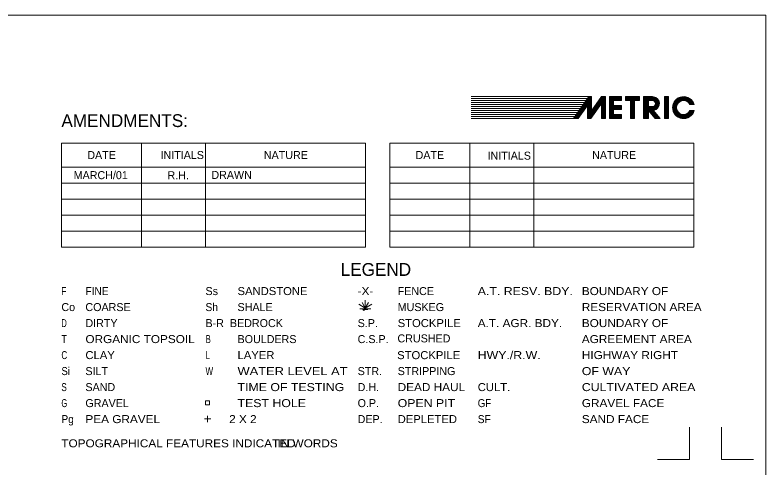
# Model space of a CAD drawing. Extents: x -496 to 480, y -450 to 700.
# Drawn here: x -19 to 450, y 416.9 to 700 of the extents above; entities that cross this region are included whole.
import ezdxf
from ezdxf.enums import TextEntityAlignment as Align

# ---------------------------------------------------------------- set-up
doc = ezdxf.new("R2010")
doc.units = 0
doc.header["$LTSCALE"] = 2
doc.header["$PDMODE"] = 32
doc.header["$PDSIZE"] = 1
doc.layers.add('1', color=7, linetype='Continuous', lineweight=13)

msp = doc.modelspace()

# ---------------------------------------------------------------- linework, layer by layer
at = {"layer": '1'}
for p, q in [((339.376, 648.989), (265.976, 648.989)), ((338.501, 647.739), (265.976, 647.739)), ((329.726, 635.239), (339.376, 648.989)), ((340.976, 640.064), (347.226, 648.989)), ((349.726, 648.989), (347.226, 648.989)), ((349.726, 635.239), (349.726, 648.989)), ((362.226, 648.989), (362.226, 646.489)), ((379.026, 648.989), (373.476, 648.989)), ((337.626, 646.489), (265.976, 646.489)), ((336.751, 645.239), (265.976, 645.239)), ((335.876, 643.989), (265.976, 643.989)), ((335.001, 642.739), (265.976, 642.739)), ((332.776, 635.239), (338.476, 643.364)), ((338.476, 635.239), (338.476, 643.389)), ((340.676, 635.264), (347.226, 644.614)), ((347.226, 635.239), (347.226, 644.614)), ((354.726, 646.489), (354.726, 643.364)), ((362.226, 646.489), (365.351, 646.489)), ((367.851, 646.489), (370.976, 646.489)), ((376.601, 646.489), (379.151, 646.489)), ((376.601, 642.739), (376.601, 646.489)), ((376.601, 642.739), (379.151, 642.739)), ((402.426, 643.989), (405.076, 643.989)), ((334.126, 641.489), (265.976, 641.489)), ((333.251, 640.239), (265.976, 640.239)), ((332.376, 638.989), (265.976, 638.989)), ((354.726, 640.864), (354.726, 637.739)), ((376.601, 640.239), (380.726, 635.239)), ((376.601, 635.239), (376.601, 640.239)), ((379.801, 640.289), (383.951, 635.239)), ((402.426, 640.239), (405.101, 640.239)), ((331.501, 637.739), (265.976, 637.739)), ((330.626, 636.489), (265.976, 636.489)), ((329.726, 635.239), (265.976, 635.239)), ((329.726, 635.239), (332.776, 635.239)), ((338.476, 635.239), (340.676, 635.239)), ((349.726, 635.239), (347.226, 635.239)), ((352.226, 635.239), (359.726, 635.239)), ((380.726, 635.239), (383.951, 635.239)), ((199.983, 619.973), (9.983, 619.973)), ((9.983, 619.973), (9.983, 554.973)), ((59.983, 619.973), (59.983, 554.973)), ((99.983, 619.973), (99.983, 554.973)), ((199.983, 554.973), (199.983, 619.973)), ((404.983, 619.973), (214.983, 619.973)), ((214.983, 619.973), (214.983, 554.973)), ((264.983, 619.973), (264.983, 554.973)), ((304.983, 619.973), (304.983, 554.973)), ((404.983, 554.973), (404.983, 619.973)), ((9.983, 604.973), (199.983, 604.973)), ((214.983, 604.973), (404.983, 604.973)), ((9.983, 594.973), (199.983, 594.973)), ((214.983, 594.973), (404.983, 594.973)), ((9.983, 584.973), (199.983, 584.973)), ((214.983, 584.973), (404.983, 584.973)), ((9.983, 574.973), (199.983, 574.973)), ((214.983, 574.973), (404.983, 574.973)), ((9.983, 564.973), (199.983, 564.973)), ((214.983, 564.973), (404.983, 564.973)), ((214.983, 554.973), (404.983, 554.973)), ((199.76, 516.875), (199.76, 521.875)), ((199.76, 516.875), (195.76, 519.375)), ((196.26, 516.375), (203.26, 516.375)), ((199.76, 516.875), (197.76, 520.375)), ((198.26, 515.875), (201.26, 515.875)), ((199.76, 516.875), (201.76, 520.375)), ((199.76, 516.875), (203.76, 519.375)), ((103.353, 447.618), (99.353, 447.618)), ((101.291, 449.597), (101.291, 445.597)), ((402.281, 422.339), (402.281, 442.339)), ((422.281, 422.339), (422.281, 442.339)), ((402.281, 422.339), (382.281, 422.339)), ((422.281, 422.339), (442.281, 422.339))]:
    msp.add_line(p, q, dxfattribs=at)
for points in [[(449.983, -450.027), (449.983, 399.973), (449.983, 699.973), (-450.017, 699.973), (-450.017, 49.973), (-450.017, -450.027)], [(329.901, 635.339), (339.401, 648.889), (340.901, 648.889), (340.901, 639.839), (347.251, 648.839), (349.626, 648.889), (349.676, 635.339), (347.351, 635.314), (347.301, 644.789), (340.576, 635.339), (338.576, 635.314), (338.576, 643.539), (332.701, 635.339), (330.076, 635.314), (339.501, 648.739), (340.801, 648.739), (340.776, 639.664), (347.276, 648.664), (349.526, 648.739), (349.651, 635.564), (347.501, 635.464), (347.426, 644.989), (340.526, 635.489), (338.726, 635.439), (338.676, 643.764), (332.651, 635.464), (330.301, 635.439), (339.576, 648.539), (340.651, 648.564), (340.651, 639.489), (347.351, 648.489), (349.301, 648.564), (349.476, 635.739), (347.726, 635.639), (347.626, 645.314), (340.451, 635.714), (338.926, 635.639), (338.876, 644.139), (332.501, 635.689), (330.701, 635.639)], [(330.701, 635.639), (339.651, 648.239), (340.326, 648.264), (340.476, 639.239), (347.526, 648.239), (349.126, 648.289), (349.226, 635.939), (348.001, 635.939), (347.851, 645.664), (340.326, 635.989), (339.151, 635.864), (339.126, 644.464), (332.401, 635.939), (331.076, 635.839), (339.651, 647.914), (340.151, 647.914), (340.251, 638.889), (347.601, 647.964), (348.926, 648.014), (349.026, 636.164), (348.251, 636.139), (348.051, 646.014), (340.226, 636.239), (339.351, 636.089), (339.326, 644.789), (332.226, 636.164), (331.476, 636.064), (339.701, 647.664), (339.926, 647.689), (340.126, 638.764), (347.751, 647.839), (348.701, 647.739), (348.826, 636.364), (348.476, 636.364), (348.176, 646.314), (340.126, 636.464), (339.551, 636.339), (339.426, 645.114), (332.201, 636.339), (331.851, 636.289)], [(331.851, 636.289), (339.701, 647.264), (339.926, 638.564), (347.826, 647.614), (348.451, 647.589), (348.701, 636.589), (348.251, 646.639), (340.126, 636.689), (339.726, 636.589), (339.576, 645.539), (332.301, 636.639), (339.526, 646.714), (339.576, 645.814), (335.101, 640.239), (339.401, 646.164), (339.401, 645.914), (338.176, 644.289)], [(340.976, 640.039), (340.976, 648.989), (339.376, 648.989)], [(339.901, 638.414), (339.926, 636.839), (348.276, 646.889), (348.326, 647.439), (347.951, 647.439), (340.126, 638.539), (340.151, 637.314), (348.176, 647.064), (348.051, 647.214), (340.326, 638.539), (340.401, 637.839), (347.851, 646.839), (340.501, 638.639), (340.526, 638.389), (344.426, 642.914)], [(352.226, 635.239), (352.226, 648.989), (359.726, 648.989)], [(352.376, 648.914), (359.651, 648.864), (359.676, 646.614), (354.626, 646.589), (354.626, 643.289), (359.651, 643.289), (359.651, 640.989), (354.651, 640.939), (354.626, 637.614), (359.676, 637.639), (359.651, 635.339), (352.351, 635.314), (352.376, 648.789), (359.551, 648.739), (359.551, 646.764), (354.501, 646.714), (354.501, 643.214), (359.551, 643.164), (359.551, 641.114), (354.551, 641.064), (354.526, 637.439), (359.551, 637.514), (359.501, 635.439), (352.501, 635.439), (352.576, 648.639), (359.401, 648.564), (359.426, 646.914), (354.376, 646.839), (354.351, 643.064), (359.426, 643.039), (359.376, 641.289), (354.401, 641.239), (354.376, 637.239), (359.401, 637.339), (359.376, 635.589), (352.701, 635.614), (352.726, 648.439), (359.226, 648.414), (359.251, 647.064), (354.251, 647.039)], [(354.251, 647.039), (354.176, 642.864), (359.251, 642.864), (359.176, 641.439), (354.251, 641.389), (354.201, 637.064), (359.201, 637.114), (359.176, 635.739), (352.926, 635.814), (352.976, 648.214), (359.026, 648.239), (359.076, 647.289), (354.076, 647.214), (354.001, 642.689), (359.051, 642.664), (359.026, 641.639), (354.076, 641.564), (354.026, 636.864), (359.051, 636.939), (359.026, 635.989), (353.126, 636.039), (353.226, 647.989), (358.801, 648.039), (358.826, 647.464), (353.926, 647.389), (353.851, 642.489), (358.876, 642.539), (358.801, 641.814), (353.951, 641.689), (353.851, 636.714), (358.901, 636.764), (358.901, 636.214), (353.351, 636.214), (353.476, 647.714), (358.601, 647.889), (358.626, 647.639), (353.776, 647.514), (353.751, 642.364), (358.626, 642.389), (358.601, 642.014)], [(358.601, 642.014), (353.826, 641.864), (353.726, 636.564), (358.701, 636.639), (358.701, 636.389), (353.551, 636.439), (353.626, 641.989), (358.376, 642.164), (358.326, 642.289), (353.576, 642.264), (353.676, 647.564)], [(359.726, 648.989), (359.726, 646.489), (354.726, 646.489)], [(370.976, 646.489), (370.976, 648.989), (362.226, 648.989)], [(362.351, 648.864), (370.851, 648.889), (370.851, 646.639), (367.701, 646.639), (367.751, 635.414), (365.451, 635.314), (365.451, 646.564), (362.351, 646.589), (362.351, 648.764), (370.801, 648.789), (370.726, 646.789), (367.601, 646.764), (367.676, 635.539), (365.576, 635.414), (365.626, 646.739), (362.476, 646.739), (362.476, 648.639), (370.626, 648.639), (370.576, 646.989), (367.426, 646.864), (367.526, 635.739), (365.751, 635.614), (365.776, 646.864), (362.701, 646.939), (362.726, 648.439), (370.451, 648.489), (370.376, 647.114), (367.276, 646.989), (367.376, 635.914), (365.901, 635.789), (365.951, 647.064), (362.901, 647.114), (362.901, 648.264), (370.201, 648.289), (370.201, 647.364), (367.076, 647.189), (367.226, 636.114), (366.126, 635.989), (366.101, 647.264), (363.101, 647.314)], [(363.101, 647.314), (363.151, 648.089), (369.976, 648.164), (369.926, 647.489), (366.876, 647.364), (367.026, 636.339), (366.351, 636.239), (366.276, 647.439), (363.326, 647.514), (363.401, 647.939), (369.751, 648.039), (369.701, 647.714), (366.726, 647.539), (366.851, 636.564), (366.476, 636.489), (366.426, 647.664), (363.701, 647.664), (363.751, 647.839), (369.451, 647.914), (369.426, 647.814), (366.601, 647.664), (366.626, 636.689)], [(373.476, 648.989), (373.476, 635.239), (376.601, 635.239)], [(373.601, 648.914), (378.976, 648.889), (380.101, 648.739), (381.101, 648.364), (381.826, 647.789), (382.451, 647.189), (382.901, 646.414), (383.301, 645.389), (383.301, 644.439), (383.126, 643.214), (382.651, 642.314), (381.926, 641.489), (381.051, 640.889), (380.401, 640.639), (379.651, 640.389), (380.026, 639.714), (380.576, 639.189), (383.701, 635.339), (380.801, 635.314), (376.501, 640.464), (376.526, 635.339), (373.551, 635.314), (373.551, 648.864), (379.026, 648.789), (380.076, 648.639), (380.926, 648.314), (382.276, 647.214), (383.151, 645.364), (383.026, 643.314), (382.601, 642.464), (381.901, 641.614), (381.051, 640.989), (379.576, 640.464), (383.501, 635.414), (380.951, 635.439), (376.351, 640.739), (376.401, 635.489), (373.701, 635.439), (373.701, 648.739), (379.151, 648.664), (380.076, 648.489), (380.851, 648.189), (382.126, 647.139), (383.026, 645.389), (382.951, 643.539), (382.501, 642.564), (381.901, 641.739), (381.051, 641.114), (379.401, 640.614), (383.201, 635.564), (381.001, 635.564), (376.226, 640.889), (376.276, 635.614), (373.826, 635.539), (373.826, 648.614), (379.126, 648.489), (380.676, 648.089), (382.026, 647.139), (382.876, 645.439), (382.801, 643.664), (382.401, 642.664), (381.801, 641.889), (380.951, 641.189), (379.226, 640.764), (382.901, 635.689), (381.101, 635.689), (376.051, 641.064), (376.126, 635.789), (373.976, 635.689), (373.976, 648.439), (379.101, 648.364), (380.551, 647.989), (381.851, 647.089), (382.776, 645.439), (382.701, 643.764), (382.326, 642.889), (381.726, 642.064), (380.901, 641.339), (379.026, 640.939), (382.601, 635.789), (381.126, 635.814), (375.876, 641.239), (375.976, 635.939), (374.126, 635.864), (374.126, 648.239), (379.026, 648.239), (380.251, 647.914), (381.676, 647.014), (382.576, 645.414), (382.601, 643.914), (382.276, 642.989), (381.651, 642.214), (380.826, 641.514), (378.851, 641.064), (382.351, 635.939), (381.176, 635.989), (375.776, 641.514), (375.826, 636.089), (374.251, 636.014), (374.276, 648.039), (378.976, 648.114)], [(378.976, 648.114), (379.026, 648.114), (380.201, 647.764), (381.526, 646.939), (382.401, 645.489), (382.401, 643.964), (382.076, 643.114), (380.826, 641.764), (378.601, 641.264), (382.001, 636.114), (381.351, 636.114), (375.676, 641.789), (375.676, 636.264), (374.376, 636.189), (374.451, 647.864), (378.926, 647.939), (380.176, 647.689), (381.351, 646.914), (382.151, 645.414), (382.201, 644.014), (381.901, 643.214), (380.726, 641.989), (378.401, 641.389), (381.676, 636.314), (381.501, 636.189), (375.526, 642.064), (375.476, 636.414), (374.551, 636.339), (374.651, 647.739), (379.976, 647.614), (381.151, 646.914), (382.001, 645.414), (382.051, 644.139), (381.726, 643.339), (380.651, 642.139), (378.226, 641.589), (381.401, 636.464), (375.401, 642.364), (375.376, 636.614), (374.676, 636.539), (374.901, 647.589), (379.826, 647.414), (380.851, 646.889), (381.801, 645.439), (381.901, 644.389), (381.576, 643.539), (380.576, 642.414), (378.051, 641.739), (380.676, 637.364), (375.376, 642.614), (375.226, 636.739), (374.851, 636.739), (375.076, 647.339), (379.601, 647.314), (380.676, 646.839), (381.626, 645.414), (381.726, 644.464), (381.376, 643.589), (380.501, 642.589), (377.826, 641.864), (380.026, 638.189), (375.251, 642.889), (375.076, 636.939), (374.926, 636.989), (375.226, 647.189), (379.526, 647.139), (380.551, 646.714), (381.401, 645.414), (381.551, 644.614), (380.376, 642.739), (377.726, 642.039), (379.276, 639.239), (375.351, 643.039), (375.426, 646.989), (379.476, 646.989), (380.526, 646.639), (381.251, 645.489), (381.326, 644.614), (380.276, 642.914), (377.551, 642.239), (378.601, 640.139), (375.576, 643.139), (375.676, 646.839), (379.451, 646.839), (380.476, 646.514), (381.101, 645.414), (381.051, 644.489), (380.876, 645.464), (380.501, 646.039), (380.151, 646.339), (379.476, 646.514), (378.751, 646.639), (377.601, 646.614), (376.476, 646.614), (376.501, 642.714), (378.626, 642.664), (377.376, 642.339), (378.126, 640.764), (375.726, 643.164), (375.876, 646.714), (379.451, 646.714)], [(386.776, 648.839), (388.951, 648.864), (389.001, 635.364), (386.701, 635.364), (386.676, 648.739), (388.851, 648.764), (388.876, 635.489), (386.826, 635.439), (386.801, 648.614), (388.776, 648.639), (388.776, 635.664), (386.976, 635.589), (386.926, 648.464), (388.626, 648.464), (388.601, 635.764), (387.126, 635.764), (387.101, 648.364), (388.501, 648.364), (388.451, 635.939), (387.301, 635.964), (387.301, 648.214), (388.401, 648.214), (388.301, 636.089), (387.426, 636.089), (387.476, 648.064), (388.251, 648.039), (388.151, 636.214), (387.576, 636.214), (387.676, 647.914), (388.126, 647.889), (388.001, 636.339), (387.776, 636.389), (387.826, 647.764), (387.976, 647.714), (387.901, 636.539)], [(404.901, 644.089), (404.451, 645.189), (403.851, 646.164), (403.151, 646.914), (402.301, 647.639), (401.151, 648.289), (400.126, 648.614), (398.801, 648.814), (397.351, 648.689), (395.876, 648.339), (394.601, 647.639), (393.601, 646.764), (392.776, 645.664), (392.176, 644.564), (391.801, 642.964), (391.801, 641.264), (392.176, 639.789), (392.726, 638.564), (393.351, 637.739), (394.101, 637.014), (394.976, 636.389), (395.901, 635.914), (397.126, 635.489), (398.726, 635.389), (400.151, 635.589), (401.301, 635.989), (402.326, 636.564), (403.326, 637.414), (404.001, 638.264), (404.426, 639.139), (404.801, 640.064), (402.526, 640.089), (401.776, 638.989), (400.776, 638.289), (399.801, 637.814), (398.476, 637.564), (397.026, 637.839), (396.126, 638.289), (395.276, 638.939), (394.551, 639.939), (394.076, 641.189), (394.051, 642.814), (394.276, 643.889), (394.901, 644.889), (395.601, 645.614), (396.476, 646.164), (397.376, 646.489), (398.426, 646.614), (399.526, 646.489), (400.426, 646.214), (401.176, 645.764), (401.801, 645.239), (402.301, 644.664), (402.576, 644.139), (404.726, 644.164), (404.251, 645.214), (403.651, 646.164), (402.276, 647.489), (401.126, 648.114), (399.351, 648.614), (397.876, 648.564), (396.551, 648.339), (395.226, 647.814), (394.351, 647.264), (393.451, 646.339), (392.676, 645.139), (392.176, 643.939), (391.976, 642.239), (392.076, 640.689), (392.576, 639.164), (393.476, 637.864), (394.526, 636.864), (395.701, 636.164), (397.201, 635.639), (398.626, 635.514), (400.251, 635.764), (401.276, 636.089), (402.301, 636.789), (403.176, 637.439), (403.726, 638.164), (404.376, 639.239), (404.551, 639.964), (402.626, 639.989), (402.076, 639.064), (400.751, 638.139), (399.826, 637.689), (398.526, 637.389), (396.976, 637.739), (395.601, 638.439), (394.651, 639.639), (394.076, 640.764), (393.876, 642.139), (394.151, 643.989), (394.726, 644.964), (395.826, 646.014), (397.051, 646.539), (398.351, 646.789), (399.826, 646.614), (401.026, 646.064), (401.701, 645.614), (402.226, 645.014)], [(402.226, 645.014), (402.301, 645.014), (402.676, 644.239), (404.476, 644.264), (404.026, 645.314), (402.876, 646.664), (401.901, 647.489), (400.851, 648.089), (399.251, 648.514), (396.976, 648.264), (395.201, 647.614), (394.051, 646.639), (393.151, 645.614), (392.526, 644.239), (392.176, 642.439), (392.326, 640.539), (392.676, 639.489), (392.951, 638.864), (393.701, 637.864), (394.851, 636.839), (397.101, 635.814), (398.651, 635.664), (401.026, 636.164), (403.076, 637.564), (403.901, 638.814), (404.326, 639.814), (403.476, 639.789), (402.726, 639.839), (402.201, 638.889), (400.776, 637.964), (399.526, 637.414), (398.251, 637.264), (396.651, 637.714), (395.476, 638.364), (394.451, 639.714), (393.901, 640.864), (393.701, 642.264), (393.976, 643.889), (394.651, 645.264), (395.701, 646.214), (397.376, 646.789), (398.851, 646.914), (400.251, 646.614), (401.626, 645.914), (402.426, 645.164), (402.801, 644.439), (404.226, 644.414), (403.426, 645.739), (402.676, 646.614), (401.826, 647.314), (400.851, 647.939), (399.276, 648.314), (397.051, 648.089), (395.226, 647.364), (393.976, 646.314), (393.201, 645.414), (392.651, 643.839), (392.426, 642.514), (392.451, 641.239), (392.651, 640.089), (393.101, 639.039), (393.651, 638.239), (394.376, 637.564), (395.226, 636.839), (396.351, 636.314), (397.451, 635.914), (398.701, 635.839), (400.826, 636.364), (402.976, 637.639), (403.801, 638.964), (404.026, 639.714), (402.851, 639.664), (402.326, 638.814), (401.226, 638.164), (399.651, 637.239), (398.226, 637.114), (397.101, 637.389), (395.976, 637.889), (394.801, 638.989), (394.101, 640.014), (393.601, 641.664), (393.676, 643.264), (394.101, 644.689), (395.376, 646.214), (396.876, 646.764), (398.751, 647.064), (400.326, 646.764), (401.751, 646.089), (402.651, 645.189), (402.951, 644.539), (403.876, 644.614), (403.051, 645.989), (402.201, 646.789), (400.851, 647.739), (399.376, 648.189), (397.151, 647.889), (395.451, 647.239), (394.076, 646.164), (393.251, 645.039), (392.701, 643.014), (392.651, 641.564)], [(392.651, 641.564), (392.676, 641.614), (392.951, 639.914), (393.451, 638.964), (394.051, 638.214), (394.926, 637.289), (395.951, 636.764), (396.601, 636.389), (397.801, 636.039), (398.776, 635.989), (400.726, 636.464), (402.951, 637.739), (403.651, 639.064), (403.726, 639.564), (403.026, 639.539), (402.576, 638.814), (399.876, 637.114), (398.026, 637.014), (396.051, 637.664), (394.476, 639.139), (393.526, 641.439), (393.651, 643.889), (394.476, 645.514), (395.726, 646.539), (397.351, 646.989), (398.701, 647.239), (400.476, 646.939), (401.751, 646.339), (402.526, 645.664), (402.851, 645.114), (403.076, 644.739), (403.551, 644.789), (402.926, 645.989), (401.801, 646.914), (400.676, 647.639), (399.376, 648.039), (397.176, 647.789), (395.676, 647.164), (394.226, 646.139), (393.501, 645.039), (392.901, 643.314), (392.826, 641.639), (393.126, 639.989), (393.851, 638.689), (394.951, 637.514), (396.001, 636.989), (396.726, 636.564), (398.626, 636.139), (400.701, 636.614), (402.776, 637.864), (403.476, 639.064), (403.601, 639.464), (403.251, 639.389), (402.751, 638.739), (400.001, 637.014), (398.001, 636.889), (395.901, 637.564), (394.326, 639.064), (393.376, 641.464), (393.576, 643.939), (394.301, 645.589), (395.526, 646.689), (398.576, 647.339), (400.751, 647.089), (401.751, 646.489), (402.601, 645.914), (403.076, 645.039), (403.326, 644.914), (402.851, 645.939), (400.926, 647.289), (399.526, 647.889), (397.401, 647.714), (395.626, 647.039), (394.251, 646.039), (393.576, 644.889), (393.026, 643.239), (392.951, 641.714), (393.276, 640.314), (393.801, 639.139), (394.376, 638.339), (395.076, 637.639), (396.901, 636.764), (398.651, 636.314), (400.576, 636.789), (402.601, 637.914), (403.351, 639.139), (402.501, 638.339), (401.601, 637.789), (400.101, 636.864), (398.051, 636.764), (395.801, 637.439), (394.176, 639.064), (393.226, 641.539), (393.501, 644.014), (394.126, 645.639), (395.451, 646.739), (397.026, 647.189), (398.576, 647.489), (399.776, 647.389), (400.526, 647.289), (399.551, 647.639)], [(399.551, 647.639), (398.601, 647.639), (397.451, 647.489), (395.901, 647.064)], [(354.726, 640.864), (359.726, 640.864), (359.726, 643.364), (354.726, 643.364)], [(367.851, 646.489), (367.851, 635.239), (365.351, 635.239), (365.351, 646.489)], [(376.026, 646.614), (375.901, 643.214), (377.551, 641.614), (377.251, 642.364), (377.776, 642.614), (376.826, 642.614), (377.201, 642.164)], [(376.151, 646.564), (376.051, 643.314), (376.376, 643.064), (376.351, 646.564), (376.251, 643.389)], [(379.451, 646.714), (379.401, 646.739), (380.451, 646.289)], [(402.751, 638.439), (402.076, 637.814), (400.676, 637.089), (399.226, 636.639), (398.501, 636.639), (396.951, 636.914), (395.751, 637.364), (394.201, 638.764), (393.101, 641.589), (393.401, 643.964), (393.901, 645.289)], [(354.726, 637.739), (359.726, 637.739), (359.726, 635.239)], [(9.983, 554.973), (99.983, 554.973), (199.983, 554.973)]]:
    msp.add_lwpolyline(points, dxfattribs=at)
for points in [[(386.601, 635.239), (386.601, 648.989), (389.101, 648.989), (389.101, 635.239)], [(99.967, 456.301), (99.967, 458.832), (102.499, 458.832), (102.499, 456.301)]]:
    msp.add_lwpolyline(points, close=True, dxfattribs=at)
for centre, radius, start, end in [((379.076, 644.614), 4.375, 279.51602, 90.65478), ((398.476, 642.114), 6.875, 15.80251, 344.19749), ((379.051, 644.614), 1.875, 272.29061, 86.94712), ((398.476, 642.114), 4.375, 25.39292, 334.60708)]:
    msp.add_arc(centre, radius, start, end, dxfattribs=at)
msp.add_point((198.76, 515.875), dxfattribs=at)

# ---------------------------------------------------------------- texts
for s, height, p in [('AMENDMENTS:', 8, (9.983, 629.973)), ('Ss', 5, (99.983, 524.973)), ('FENCE', 5, (219.983, 524.973)), ('Co', 5, (9.983, 514.973)), ('COARSE', 5, (24.983, 514.973)), ('SHALE', 5, (119.983, 514.973)), ('MUSKEG', 5, (219.983, 514.973)), ('DIRTY', 5, (24.983, 504.973)), ('B-R  BEDROCK', 5, (99.983, 504.973)), ('S.P.', 5, (194.983, 504.973)), ('BOULDERS', 5, (119.983, 494.973)), ('C.S.P.', 5, (194.983, 494.973)), ('CRUSHED', 5, (219.856, 495.402)), ('SILT', 5, (24.983, 474.973)), ('STR.', 5, (194.983, 474.973)), ('STRIPPING', 5, (219.983, 474.973)), ('SAND', 5, (24.983, 464.973)), ('D.H.', 5, (194.983, 464.973)), ('GRAVEL', 5, (24.983, 454.973)), ('O.P.', 5, (194.983, 454.973)), ('DEP.', 5, (194.983, 444.973))]:
    msp.add_text(s, height=height, dxfattribs=at).set_placement(p)
for s, height, p in [('DATE', 5, (35.081, 609.973)), ('INITIALS', 5, (85.453, 609.973)), ('NATURE', 5, (150.16, 609.973)), ('DATE', 5, (240.081, 609.973)), ('INITIALS', 5, (289.66, 609.584)), ('NATURE', 5, (355.16, 609.973)), ('MARCH/01', 5, (34.552, 597.405)), ('R.H.', 5, (82.941, 597.343)), ('DRAWN', 5, (116.266, 597.567)), ('LEGEND', 8, (206.378, 536.973))]:
    msp.add_text(s, height=height, dxfattribs=at).set_placement(p, align=Align.CENTER)
for s, width, p in [('F', 0.75, (9.983, 524.973)), ('FINE', 0.95, (24.983, 524.973)), ('SANDSTONE', 1.05, (119.983, 524.973)), ('-X-', 1.1, (194.983, 524.973)), ('A.T. RESV. BDY.', 1.15, (269.983, 524.973)), ('BOUNDARY OF', 1.1, (334.983, 524.973)), ('Sh', 0.95, (99.983, 514.973)), ('RESERVATION AREA', 1.1, (334.983, 514.973)), ('D', 0.7, (9.983, 504.973)), ('STOCKPILE', 1.05, (219.983, 504.973)), ('A.T. AGR. BDY.', 1.1, (269.983, 504.973)), ('BOUNDARY OF', 1.1, (334.983, 504.973)), ('T', 0.85, (9.983, 494.973)), ('ORGANIC TOPSOIL', 1.1, (24.983, 494.973)), ('B', 0.75, (99.983, 494.973)), ('AGREEMENT AREA', 1.1, (334.983, 494.973)), ('C', 0.75, (9.983, 484.973)), ('CLAY', 1.05, (24.983, 484.973)), ('L', 0.75, (99.983, 484.973)), ('LAYER', 1.05, (119.983, 484.973)), ('STOCKPILE', 1.05, (219.649, 484.941)), ('HWY./R.W.', 1.15, (269.983, 484.973)), ('HIGHWAY RIGHT', 1.1, (334.983, 484.973)), ('Si', 0.9, (9.983, 474.973)), ('W', 0.75, (99.983, 474.973)), ('WATER LEVEL AT', 1.2, (119.983, 474.973)), ('OF WAY', 1.15, (334.983, 474.973)), ('S', 0.75, (9.983, 464.973)), ('TIME OF TESTING', 1.15, (119.983, 464.973)), ('DEAD HAUL', 1.1, (219.983, 464.973)), ('CULT.', 1.05, (269.983, 464.973)), ('CULTIVATED AREA', 1.15, (334.983, 464.973)), ('G', 0.7, (9.983, 454.973)), ('TEST HOLE', 1.15, (119.983, 454.973)), ('OPEN PIT', 1.15, (219.983, 454.973)), ('GF', 0.9, (269.983, 454.973)), ('GRAVEL FACE', 1.1, (334.983, 454.973)), ('Pg', 0.95, (9.983, 444.973)), ('PEA GRAVEL', 1.1, (24.983, 444.973)), ('   2 X 2', 1.1, (108.608, 444.973)), ('DEPLETED', 1.05, (219.983, 444.973)), ('SF', 0.95, (269.983, 444.973)), ('SAND FACE', 1.1, (334.983, 444.973)), ('TOPOGRAPHICAL FEATURES INDICATED', 1.1, (9.942, 429.855)), ('IN WORDS', 1.1, (144.942, 429.855))]:
    msp.add_text(s, height=5, dxfattribs=dict(at, width=width)).set_placement(p)

doc.saveas('drawing.dxf')
